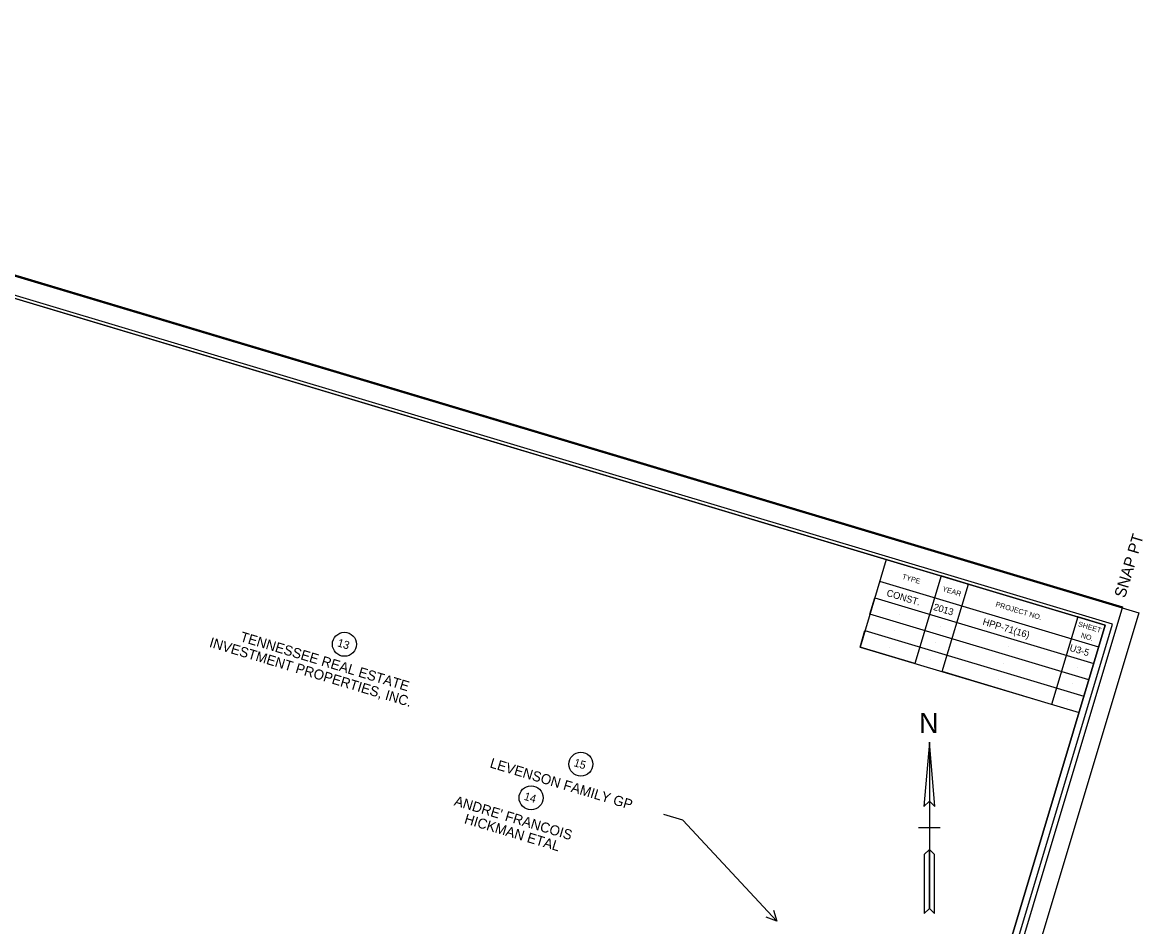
# Model space of a CAD drawing. Extents: x 2627582 to 2629622, y 568931 to 570612.
# Drawn here: x 2628642 to 2629622, y 569779 to 570571 of the extents above; entities that cross this region are included whole.
import ezdxf

# ---------------------------------------------------------------- set-up
doc = ezdxf.new("R2010")
doc.units = 0
for name, color, linetype in [('DESIGN - CENTERLINE - Proposed Text', 7, 'Continuous'), ('DESIGN - SCRATCH - User 1', 7, 'Continuous'), ('DESIGN - SHEET - Corner Text', 7, 'Continuous'), ('DESIGN - SHEET - Light Grid', 7, 'Continuous'), ('DESIGN - SHEET - Linework', 7, 'Continuous'), ('DESIGN - SHEET - Plot Shape', 7, 'Continuous'), ('SURVEY - PROPERTY - Owners', 7, 'Continuous'), ('SURVEY - PROPERTY - Tract Numbers', 7, 'Continuous')]:
    doc.layers.add(name, color=color, linetype=linetype)

msp = doc.modelspace()

# ---------------------------------------------------------------- linework, layer by layer
at = {"layer": 'DESIGN - CENTERLINE - Proposed Text'}
for p, q in [((2629435.34, 569865.62), (2629425.89, 569865.62)), ((2629444.79, 569865.62), (2629435.34, 569865.62))]:
    msp.add_line(p, q, dxfattribs=at)
msp.add_lwpolyline([(2629435.34, 569940.62), (2629430.44, 569884.32), (2629435.34, 569889.22), (2629440.24, 569884.32), (2629435.34, 569940.62), (2629435.34, 569795.17), (2629439.89, 569790.62), (2629439.89, 569842.37), (2629435.34, 569846.92), (2629430.79, 569842.37), (2629430.79, 569790.62), (2629435.34, 569795.17)], dxfattribs=at)
for points in [[(2629435.34, 569889.22), (2629440.24, 569884.32), (2629435.34, 569940.62)], [(2629430.79, 569790.62), (2629435.34, 569795.17), (2629435.34, 569846.92), (2629430.79, 569842.37)]]:
    msp.add_lwpolyline(points, close=True, dxfattribs=at)
at = {"layer": 'DESIGN - SCRATCH - User 1'}
for p, q in [((2629413.7, 570067.08), (2629413.7, 570067.08)), ((2629409.4, 570052.72), (2629409.4, 570052.72)), ((2629449.14, 570056.46), (2629449.14, 570056.46)), ((2629444.84, 570042.09), (2629444.84, 570042.09)), ((2629405.09, 570038.35), (2629405.09, 570038.35)), ((2629509.01, 570038.51), (2629509.01, 570038.51)), ((2629400.78, 570023.98), (2629400.78, 570023.98)), ((2629440.53, 570027.72), (2629440.53, 570027.72)), ((2629504.71, 570024.15), (2629504.71, 570024.15)), ((2629568.88, 570020.57), (2629568.88, 570020.57)), ((2629436.22, 570013.36), (2629436.22, 570013.36)), ((2629500.4, 570009.78), (2629500.4, 570009.78)), ((2629564.57, 570006.2), (2629564.57, 570006.2)), ((2629496.09, 569995.41), (2629496.09, 569995.41)), ((2629560.27, 569991.83), (2629560.27, 569991.83)), ((2629555.96, 569977.46), (2629555.96, 569977.46))]:
    msp.add_line(p, q, dxfattribs=at)
at = {"layer": 'DESIGN - SHEET - Light Grid'}
msp.add_lwpolyline([(2627697.64, 569511.43), (2629292.52, 569033.35), (2629595.46, 570043.92), (2628000.57, 570522.01)], close=True, dxfattribs=at)
at = {"layer": 'DESIGN - SHEET - Linework'}
for p, q in [((2627894.35, 570570.76), (2629618.55, 570053.91)), ((2629618.55, 570053.91), (2629306.31, 569012.3))]:
    msp.add_line(p, q, dxfattribs=at)
for points in [[(2628081.32, 570495.19), (2627779.83, 569489.41), (2629287.73, 569037.39), (2629589.23, 570043.18), (2628081.32, 570495.19)], [(2629397.65, 570100.61), (2629374.68, 570023.97), (2629566.26, 569966.55), (2629589.23, 570043.18), (2629565.28, 570050.36), (2629542.31, 569973.72), (2629446.52, 570002.44), (2629469.49, 570079.07), (2629445.55, 570086.25), (2629422.58, 570009.62), (2629374.68, 570023.97), (2629378.99, 570038.34), (2629570.57, 569980.91), (2629574.87, 569995.28), (2629383.29, 570052.71), (2629387.6, 570067.08), (2629579.18, 570009.65), (2629583.49, 570024.02), (2629391.91, 570081.45)]]:
    msp.add_lwpolyline(points, dxfattribs=at)
at = {"layer": 'DESIGN - SHEET - Plot Shape'}
for points in [[(2627975.91, 570547.35), (2629604.32, 570059.22), (2629291.51, 569015.7), (2627663.1, 569503.83)], [(2627999.85, 570519.61), (2629589.23, 570043.18), (2629287.73, 569037.39), (2627698.36, 569513.83)]]:
    msp.add_lwpolyline(points, close=True, dxfattribs=at)
at = {"layer": 'SURVEY - PROPERTY - Tract Numbers'}
for points in [[(2629219.73, 569872.44), (2629202.96, 569877.47)], [(2629301.81, 569784.18), (2629219.73, 569872.44)], [(2629299.05, 569793.57), (2629301.81, 569784.18), (2629292.65, 569787.61)]]:
    msp.add_lwpolyline(points, dxfattribs=at)
for centre in [(2628923.49, 570026.4), (2629130.39, 569921.48), (2629086.82, 569892.04)]:
    msp.add_circle(centre, 10.5, dxfattribs=at)

# ---------------------------------------------------------------- texts
at = {"layer": 'DESIGN - CENTERLINE - Proposed Text'}
msp.add_text('N', height=17.72, dxfattribs=at).set_placement((2629426.29, 569948.67))
at = {"layer": 'DESIGN - SHEET - Corner Text'}
for s, height, rotation, p in [('  SNAP PT', 10, 73.31329, (2629604.32, 570059.22)), ('TYPE', 4.5, 343.31329, (2629411.1, 570083.84)), ('CONST.', 6, 343.31329, (2629397.37, 570068.85)), ('YEAR', 4.5, 343.31329, (2629446.3, 570073.08)), ('2013', 6, 343.31329, (2629438.33, 570056.57)), ('PROJECT NO.', 4.5, 343.31329, (2629492.87, 570059.54)), ('HPP-71(16)', 6, 343.31329, (2629481.46, 570043.64)), ('SHEET', 4.5, 343.31329, (2629565.09, 570042.22)), ('NO.', 4.5, 343.31329, (2629567.52, 570032.41)), ('U3-5', 6, 343.31329, (2629557.5, 570020.85))]:
    msp.add_text(s, height=height, rotation=rotation, dxfattribs=at).set_placement(p)
at = {"layer": 'SURVEY - PROPERTY - Owners'}
for s, p in [('INVESTMENT PROPERTIES, INC.', (2628804.66, 570024.29)), ('TENNESSEE REAL ESTATE', (2628831.6, 570029.26)), ('LEVENSON FAMILY GP', (2629050.15, 569918.71)), ("ANDRE' FRANCOIS", (2629018.88, 569885.58)), ('HICKMAN ETAL', (2629027.76, 569869.87))]:
    msp.add_text(s, height=8.75, rotation=343.31329, dxfattribs=at).set_placement(p)
at = {"layer": 'SURVEY - PROPERTY - Tract Numbers'}
for s, p in [('13', (2628916.73, 570024.77)), ('15', (2629123.63, 569919.86)), ('14', (2629080.06, 569890.42))]:
    msp.add_text(s, height=7, rotation=343.31329, dxfattribs=at).set_placement(p)

doc.saveas('drawing.dxf')
